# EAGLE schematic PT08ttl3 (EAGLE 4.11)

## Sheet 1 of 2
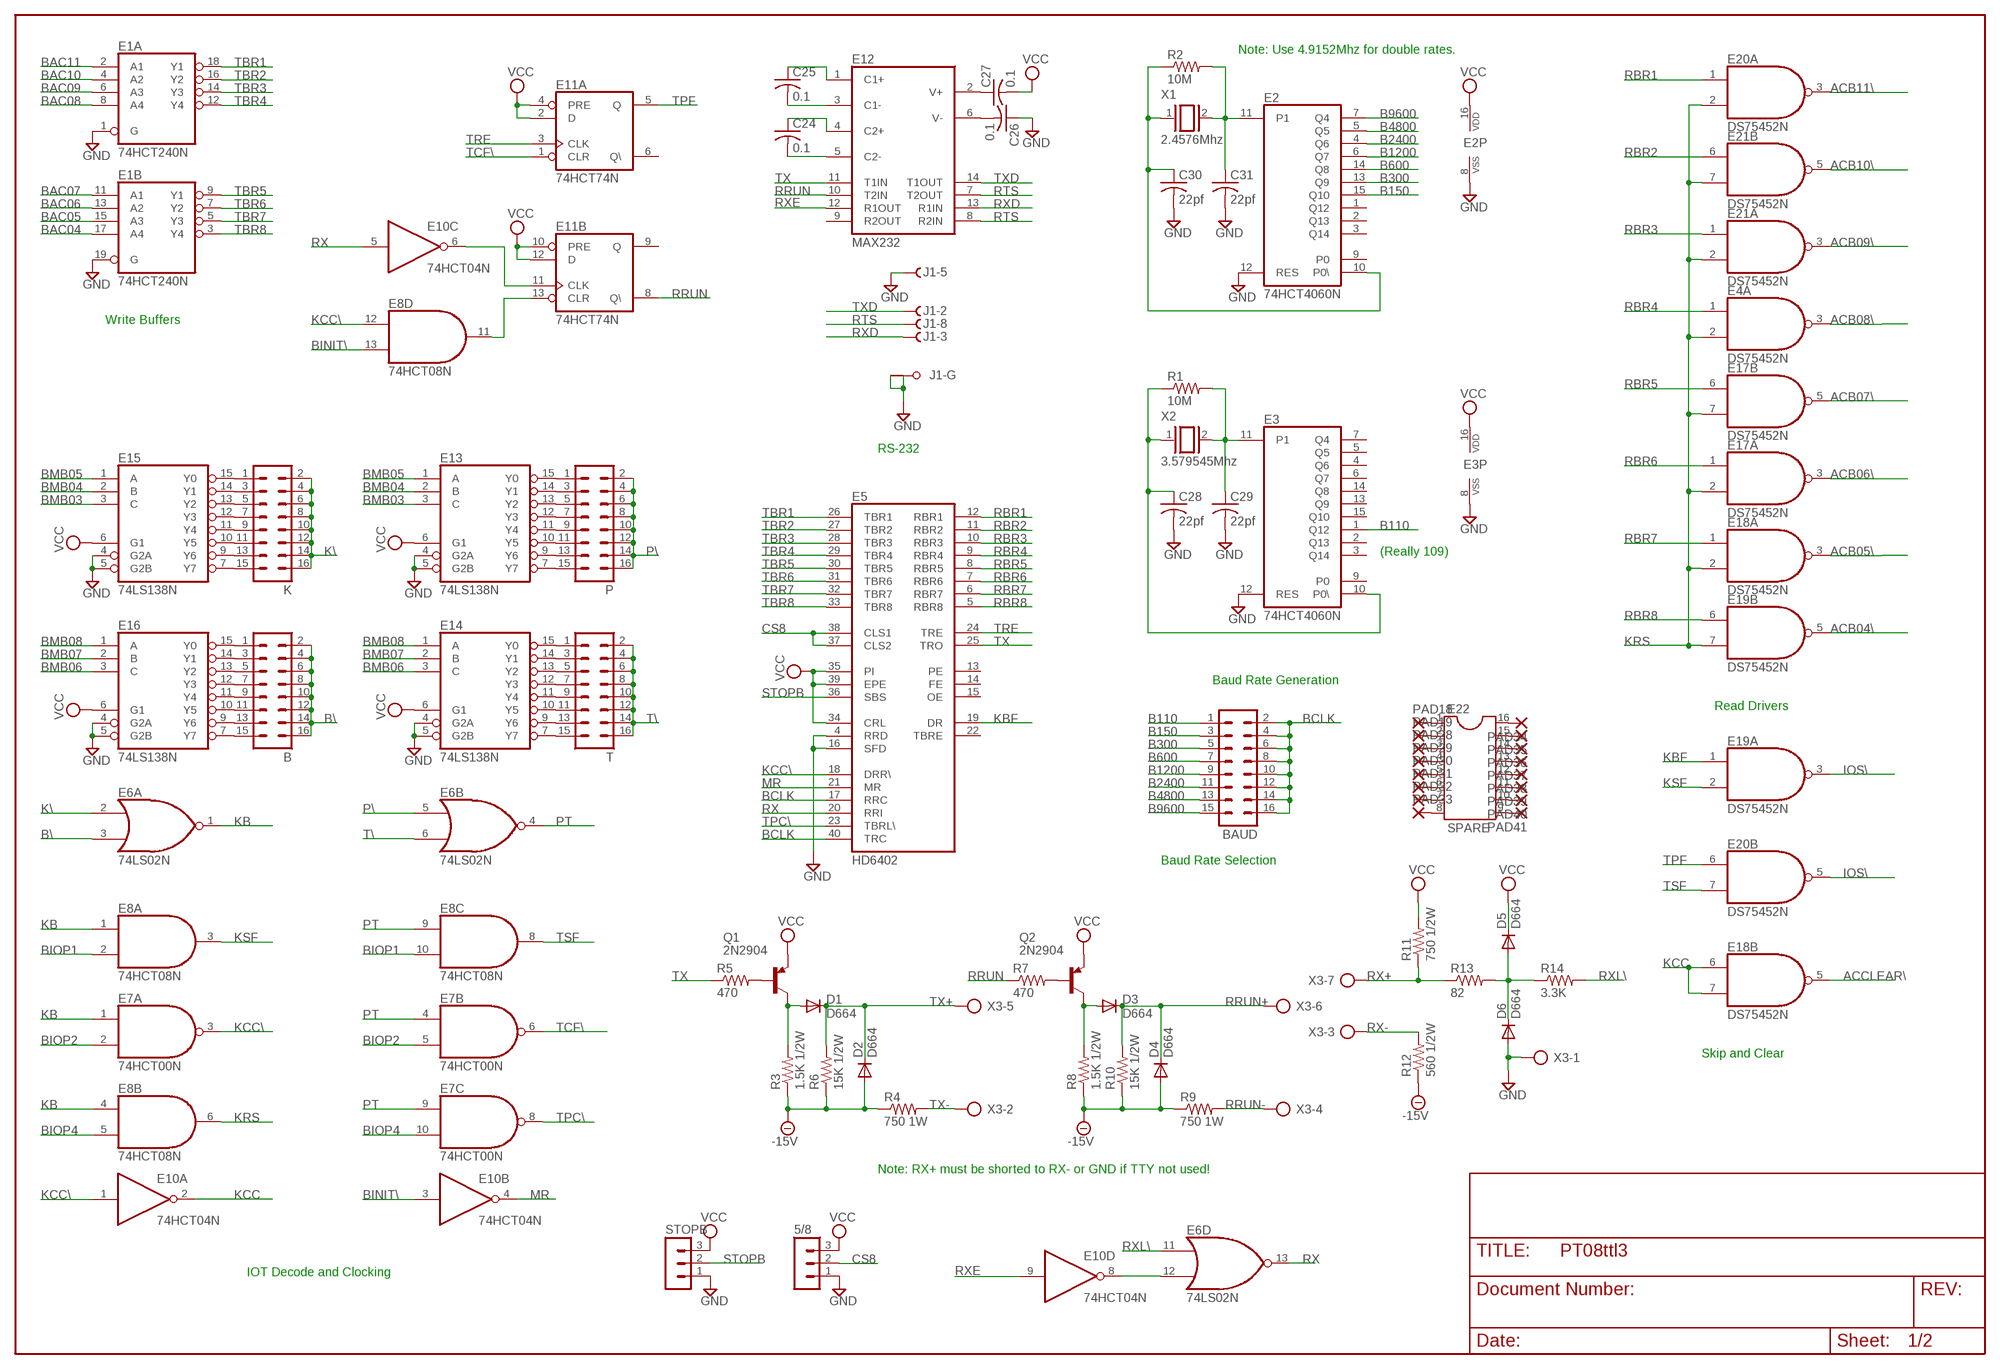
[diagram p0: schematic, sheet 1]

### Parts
5/8  MA03-1  [MA03-1]
B  MA08-2  [MA08-2]
BAUD  MA08-2  [MA08-2]
C24  0.1  C-US050-025X075  [C050-025X075]
C25  0.1  C-US050-025X075  [C050-025X075]
C26  0.1  C-US050-025X075  [C050-025X075]
C27  0.1  C-US050-025X075  [C050-025X075]
C28  22pf  C-US050-025X075  [C050-025X075]
C29  22pf  C-US050-025X075  [C050-025X075]
C30  22pf  C-US050-025X075  [C050-025X075]
C31  22pf  C-US050-025X075  [C050-025X075]
D1  D664  1N4148  [DO35-10]
D2  D664  1N4148  [DO35-10]
D3  D664  1N4148  [DO35-10]
D4  D664  1N4148  [DO35-10]
D5  D664  1N4148  [DO35-10]
D6  D664  1N4148  [DO35-10]
E1  74HCT240N  [DIL20]
E2  74HCT4060N  4060N  [DIL16]
E3  74HCT4060N  4060N  [DIL16]
E4  DS75452N  [DIL08]
E5  HD6402  [DIL40]
E6  74LS02N  [DIL14]
E7  74HCT00N  [DIL14]
E8  74HCT08N  [DIL14]
E10  74HCT04N  [DIL14]
E11  74HCT74N  [DIL14]
E12  MAX232  [DIL16]
E13  74LS138N  [DIL16]
E14  74LS138N  [DIL16]
E15  74LS138N  [DIL16]
E16  74LS138N  [DIL16]
E17  DS75452N  [DIL08]
E18  DS75452N  [DIL08]
E19  DS75452N  [DIL08]
E20  DS75452N  [DIL08]
E21  DS75452N  [DIL08]
E22  SPARE  DIL16  [DIL16]
J1  F09HPS  [F09HP]
K  MA08-2  [MA08-2]
P  MA08-2  [MA08-2]
PAD18  1,6/0,8  [1,6/0,8]
PAD19  1,6/0,8  [1,6/0,8]
PAD28  1,6/0,8  [1,6/0,8]
PAD29  1,6/0,8  [1,6/0,8]
PAD30  1,6/0,8  [1,6/0,8]
PAD31  1,6/0,8  [1,6/0,8]
PAD32  1,6/0,8  [1,6/0,8]
PAD33  1,6/0,8  [1,6/0,8]
PAD34  1,6/0,8  [1,6/0,8]
PAD35  1,6/0,8  [1,6/0,8]
PAD36  1,6/0,8  [1,6/0,8]
PAD37  1,6/0,8  [1,6/0,8]
PAD38  1,6/0,8  [1,6/0,8]
PAD39  1,6/0,8  [1,6/0,8]
PAD40  1,6/0,8  [1,6/0,8]
PAD41  1,6/0,8  [1,6/0,8]
Q1  2N2904  [TO39]
Q2  2N2904  [TO39]
R1  10M  R-US_0207/10  [0207/10]
R2  10M  R-US_0207/10  [0207/10]
R3  1.5K 1/2W  R-US_0207/10  [0207/10]
R4  750 1W  R-US_0207/10  [0207/10]
R5  470  R-US_0207/10  [0207/10]
R6  15K 1/2W  R-US_0207/10  [0207/10]
R7  470  R-US_0207/10  [0207/10]
R8  1.5K 1/2W  R-US_0207/10  [0207/10]
R9  750 1W  R-US_0207/10  [0207/10]
R10  15K 1/2W  R-US_0207/10  [0207/10]
R11  750 1/2W  R-US_0207/10  [0207/10]
R12  560 1/2W  R-US_0207/10  [0207/10]
R13  82  R-US_0207/10  [0207/10]
R14  3.3K  R-US_0207/10  [0207/10]
STOPB  MA03-1  [MA03-1]
T  MA08-2  [MA08-2]
X1  2.4576Mhz  XTAL/S  [QS]
X2  3.579545Mhz  XTAL/S  [QS]
X3  AK300/7  [AK300/7]

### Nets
-15V [supply]: D2.A D4.A R3.1 R4.1 R6.1 R8.1 R9.1 R10.1 R12.1 ; also sheet 2
ACB04\: E19.5(B:O) ; also sheet 2
ACB05\: E18.3(A:O) ; also sheet 2
ACB06\: E17.3(A:O) ; also sheet 2
ACB07\: E17.5(B:O) ; also sheet 2
ACB08\: E4.3(A:O) ; also sheet 2
ACB09\: E21.3(A:O) ; also sheet 2
ACB10\: E21.5(B:O) ; also sheet 2
ACB11\: E20.3(A:O) ; also sheet 2
ACCLEAR\: E18.5(B:O) ; also sheet 2
B110: BAUD.1 E3.1(Q12)
B150: BAUD.3 E2.15(Q10)
B300: BAUD.5 E2.13(Q9)
B600: BAUD.7 E2.14(Q8)
B1200: BAUD.9 E2.6(Q7)
B2400: BAUD.11 E2.4(Q6)
B4800: BAUD.13 E2.5(Q5)
B9600: BAUD.15 E2.7(Q4)
B\: B.2 B.4 B.6 B.8 B.10 B.12 B.14 B.16 E6.3(A:I1)
BAC04: E1.17(B:A4) ; also sheet 2
BAC05: E1.15(B:A3) ; also sheet 2
BAC06: E1.13(B:A2) ; also sheet 2
BAC07: E1.11(B:A1) ; also sheet 2
BAC08: E1.8(A:A4) ; also sheet 2
BAC09: E1.6(A:A3) ; also sheet 2
BAC10: E1.4(A:A2) ; also sheet 2
BAC11: E1.2(A:A1) ; also sheet 2
BCLK: BAUD.2 BAUD.4 BAUD.6 BAUD.8 BAUD.10 BAUD.12 BAUD.14 BAUD.16 E5.17(RRC) E5.40(TRC)
BINIT\: E8.13(D:I1) E10.3(B:I) ; also sheet 2
BIOP1: E8.2(A:I1) E8.10(C:I1) ; also sheet 2
BIOP2: E7.2(A:I1) E7.5(B:I1) ; also sheet 2
BIOP4: E7.10(C:I1) E8.5(B:I1) ; also sheet 2
BMB03: E13.3(C) E15.3(C) ; also sheet 2
BMB04: E13.2(B) E15.2(B) ; also sheet 2
BMB05: E13.1(A) E15.1(A) ; also sheet 2
BMB06: E14.3(C) E16.3(C) ; also sheet 2
BMB07: E14.2(B) E16.2(B) ; also sheet 2
BMB08: E14.1(A) E16.1(A) ; also sheet 2
CS8: 5/8.2 E5.37(CLS2) E5.38(CLS1)
GND [supply]: 5/8.1 C26.1 C28.2 C29.2 C30.2 C31.2 D6.A E1.1(A:G) E1.19(B:G) E2.8(VSS) E2.12(RES) E3.8(VSS) E3.12(RES) E5.4(RRD) E5.16(SFD) E13.4(G2A) E13.5(G2B) E14.4(G2A) E14.5(G2B) E15.4(G2A) E15.5(G2B) E16.4(G2A) E16.5(G2B) J1.5(-5:F) J1.G1(-G:G1) J1.G2(-G:G2) STOPB.1 X3.1 ; also sheet 2
IOS\: E19.3(A:O) E20.5(B:O) ; also sheet 2
K\: E6.2(A:I0) K.2 K.4 K.6 K.8 K.10 K.12 K.14 K.16
KB: E6.1(A:O) E7.1(A:I0) E8.1(A:I0) E8.4(B:I0)
KBF: E5.19(DR) E19.1(A:I0) ; also sheet 2
KCC: E10.2(A:O) E18.6(B:I0) E18.7(B:I1)
KCC\: E5.18(DRR\) E7.3(A:O) E8.12(D:I0) E10.1(A:I)
KRS: E4.2(A:I1) E8.6(B:O) E17.2(A:I1) E17.7(B:I1) E18.2(A:I1) E19.7(B:I1) E20.2(A:I1) E21.2(A:I1) E21.7(B:I1)
KSF: E8.3(A:O) E19.2(A:I1)
MR: E5.21(MR) E10.4(B:O)
N$1: B.13 E16.9(Y6)
N$5: B.1 E16.15(Y0)
N$6: B.3 E16.14(Y1)
N$7: B.5 E16.13(Y2)
N$8: B.7 E16.12(Y3)
N$9: B.9 E16.11(Y4)
N$10: B.11 E16.10(Y5)
N$11: B.15 E16.7(Y7)
N$13: C29.1 E3.11(P1) R1.2 X2.2
N$14: C28.1 E3.10(P0\) R1.1 X2.1
N$15 [supply]: C26.2 E12.6(V-)
N$16 [supply]: C27.1 E12.2(V+)
N$17: Q1.2(B) R5.2
N$18: D1.A Q1.3(C) R3.2
N$19: Q2.2(B) R7.2
N$20: D3.A Q2.3(C) R8.2
N$22: C24.2 E12.5(C2-)
N$23: C30.1 E2.10(P0\) R2.1 X1.1
N$24: D5.A D6.C R13.2 R14.1
N$25: C31.1 E2.11(P1) R2.2 X1.2
N$26: E8.11(D:O) E11.13(B:CLR)
N$27: E6.12(D:I1) E10.8(D:O)
N$29: E10.6(C:O) E11.11(B:CLK)
N$32: C25.2 E12.3(C1-)
N$34: E22.1 PAD18.1(P)
N$41: E22.2 PAD19.1(P)
N$43: E22.3 PAD28.1(P)
N$44: C24.1 E12.4(C2+)
N$45: C25.1 E12.1(C1+)
N$49: E14.15(Y0) T.1
N$50: E22.4 PAD29.1(P)
N$51: E22.5 PAD30.1(P)
N$52: E22.6 PAD31.1(P)
N$53: E22.7 PAD32.1(P)
N$54: E22.8 PAD33.1(P)
N$55: E22.16 PAD34.1(P)
N$56: E22.15 PAD35.1(P)
N$57: E22.14 PAD36.1(P)
N$58: E22.13 PAD37.1(P)
N$59: E22.12 PAD38.1(P)
N$61: E22.11 PAD39.1(P)
N$68: E22.10 PAD40.1(P)
N$69: E22.9 PAD41.1(P)
N$90: E15.15(Y0) K.1
N$91: E15.14(Y1) K.3
N$97: E15.13(Y2) K.5
N$109: E15.12(Y3) K.7
N$112: E15.11(Y4) K.9
N$113: E15.10(Y5) K.11
N$114: E15.7(Y7) K.15
N$115: E15.9(Y6) K.13
N$116: E14.14(Y1) T.3
N$117: E14.13(Y2) T.5
N$118: E14.12(Y3) T.7
N$119: E14.11(Y4) T.9
N$120: E14.10(Y5) T.11
N$121: E14.7(Y7) T.15
N$122: E14.9(Y6) T.13
N$123: E13.15(Y0) P.1
N$124: E13.14(Y1) P.3
N$125: E13.13(Y2) P.5
N$126: E13.12(Y3) P.7
N$127: E13.11(Y4) P.9
N$128: E13.10(Y5) P.11
N$129: E13.7(Y7) P.15
N$130: E13.9(Y6) P.13
P\: E6.5(B:I0) P.2 P.4 P.6 P.8 P.10 P.12 P.14 P.16
PT: E6.4(B:O) E7.4(B:I0) E7.9(C:I0) E8.9(C:I0)
RBR1: E5.12(RBR1) E20.1(A:I0)
RBR2: E5.11(RBR2) E21.6(B:I0)
RBR3: E5.10(RBR3) E21.1(A:I0)
RBR4: E4.1(A:I0) E5.9(RBR4)
RBR5: E5.8(RBR5) E17.6(B:I0)
RBR6: E5.7(RBR6) E17.1(A:I0)
RBR7: E5.6(RBR7) E18.1(A:I0)
RBR8: E5.5(RBR8) E19.6(B:I0)
RRUN: E11.8(B:Q\) E12.10(T2IN) R7.1
RRUN+: D3.C D4.C R10.2 X3.6
RRUN-: R9.2 X3.4
RTS: E12.7(T2OUT) E12.8(R2IN) J1.8(-8:F)
RX: E5.20(RRI) E6.13(D:O) E10.5(C:I)
RX+: R11.1 R13.1 X3.7
RX-: R12.2 X3.3
RXD: E12.13(R1IN) J1.3(-3:F)
RXE: E10.9(D:I) E12.12(R1OUT)
RXL\: E6.11(D:I0) R14.2
STOPB: E5.36(SBS) STOPB.2
T\: E6.6(B:I1) T.2 T.4 T.6 T.8 T.10 T.12 T.14 T.16
TBR1: E1.18(A:Y1) E5.26(TBR1)
TBR2: E1.16(A:Y2) E5.27(TBR2)
TBR3: E1.14(A:Y3) E5.28(TBR3)
TBR4: E1.12(A:Y4) E5.29(TBR4)
TBR5: E1.9(B:Y1) E5.30(TBR5)
TBR6: E1.7(B:Y2) E5.31(TBR6)
TBR7: E1.5(B:Y3) E5.32(TBR7)
TBR8: E1.3(B:Y4) E5.33(TBR8)
TCF\: E7.6(B:O) E11.1(A:CLR)
TPC\: E5.23(TBRL\) E7.8(C:O)
TPF: E11.5(A:Q) E20.6(B:I0) ; also sheet 2
TRE: E5.24(TRE) E11.3(A:CLK)
TSF: E8.8(C:O) E20.7(B:I1)
TX: E5.25(TRO) E12.11(T1IN) R5.1
TX+: D1.C D2.C R6.2 X3.5
TX-: R4.2 X3.2
TXD: E12.14(T1OUT) J1.2(-2:F)
VCC [supply]: 5/8.3 C27.2 D5.C E2.16(VDD) E3.16(VDD) E5.34(CRL) E5.35(PI) E5.39(EPE) E11.2(A:D) E11.4(A:PRE) E11.10(B:PRE) E11.12(B:D) E13.6(G1) E14.6(G1) E15.6(G1) E16.6(G1) Q1.1(E) Q2.1(E) R11.2 STOPB.3 ; also sheet 2
Unconnected: E2.1(Q12) E2.2(Q13) E2.3(Q14) E2.9(P0) E3.2(Q13) E3.3(Q14) E3.4(Q6) E3.5(Q5) E3.6(Q7) E3.7(Q4) E3.9(P0) E3.13(Q9) E3.14(Q8) E3.15(Q10) E5.13(PE) E5.14(FE) E5.15(OE) E5.22(TBRE) E11.6(A:Q\) E11.9(B:Q) E12.9(R2OUT) J1.1(-1:F) J1.4(-4:F) J1.6(-6:F) J1.7(-7:F) J1.9(-9:F)

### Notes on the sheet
- Note: Use 4.9152Mhz for double rates.
- Write Buffers
- RS-232
- (Really 109)
- Baud Rate Generation
- Read Drivers
- Baud Rate Selection
- Skip and Clear
- Note: RX+ must be shorted to RX- or GND if TTY not used!
- IOT Decode and Clocking

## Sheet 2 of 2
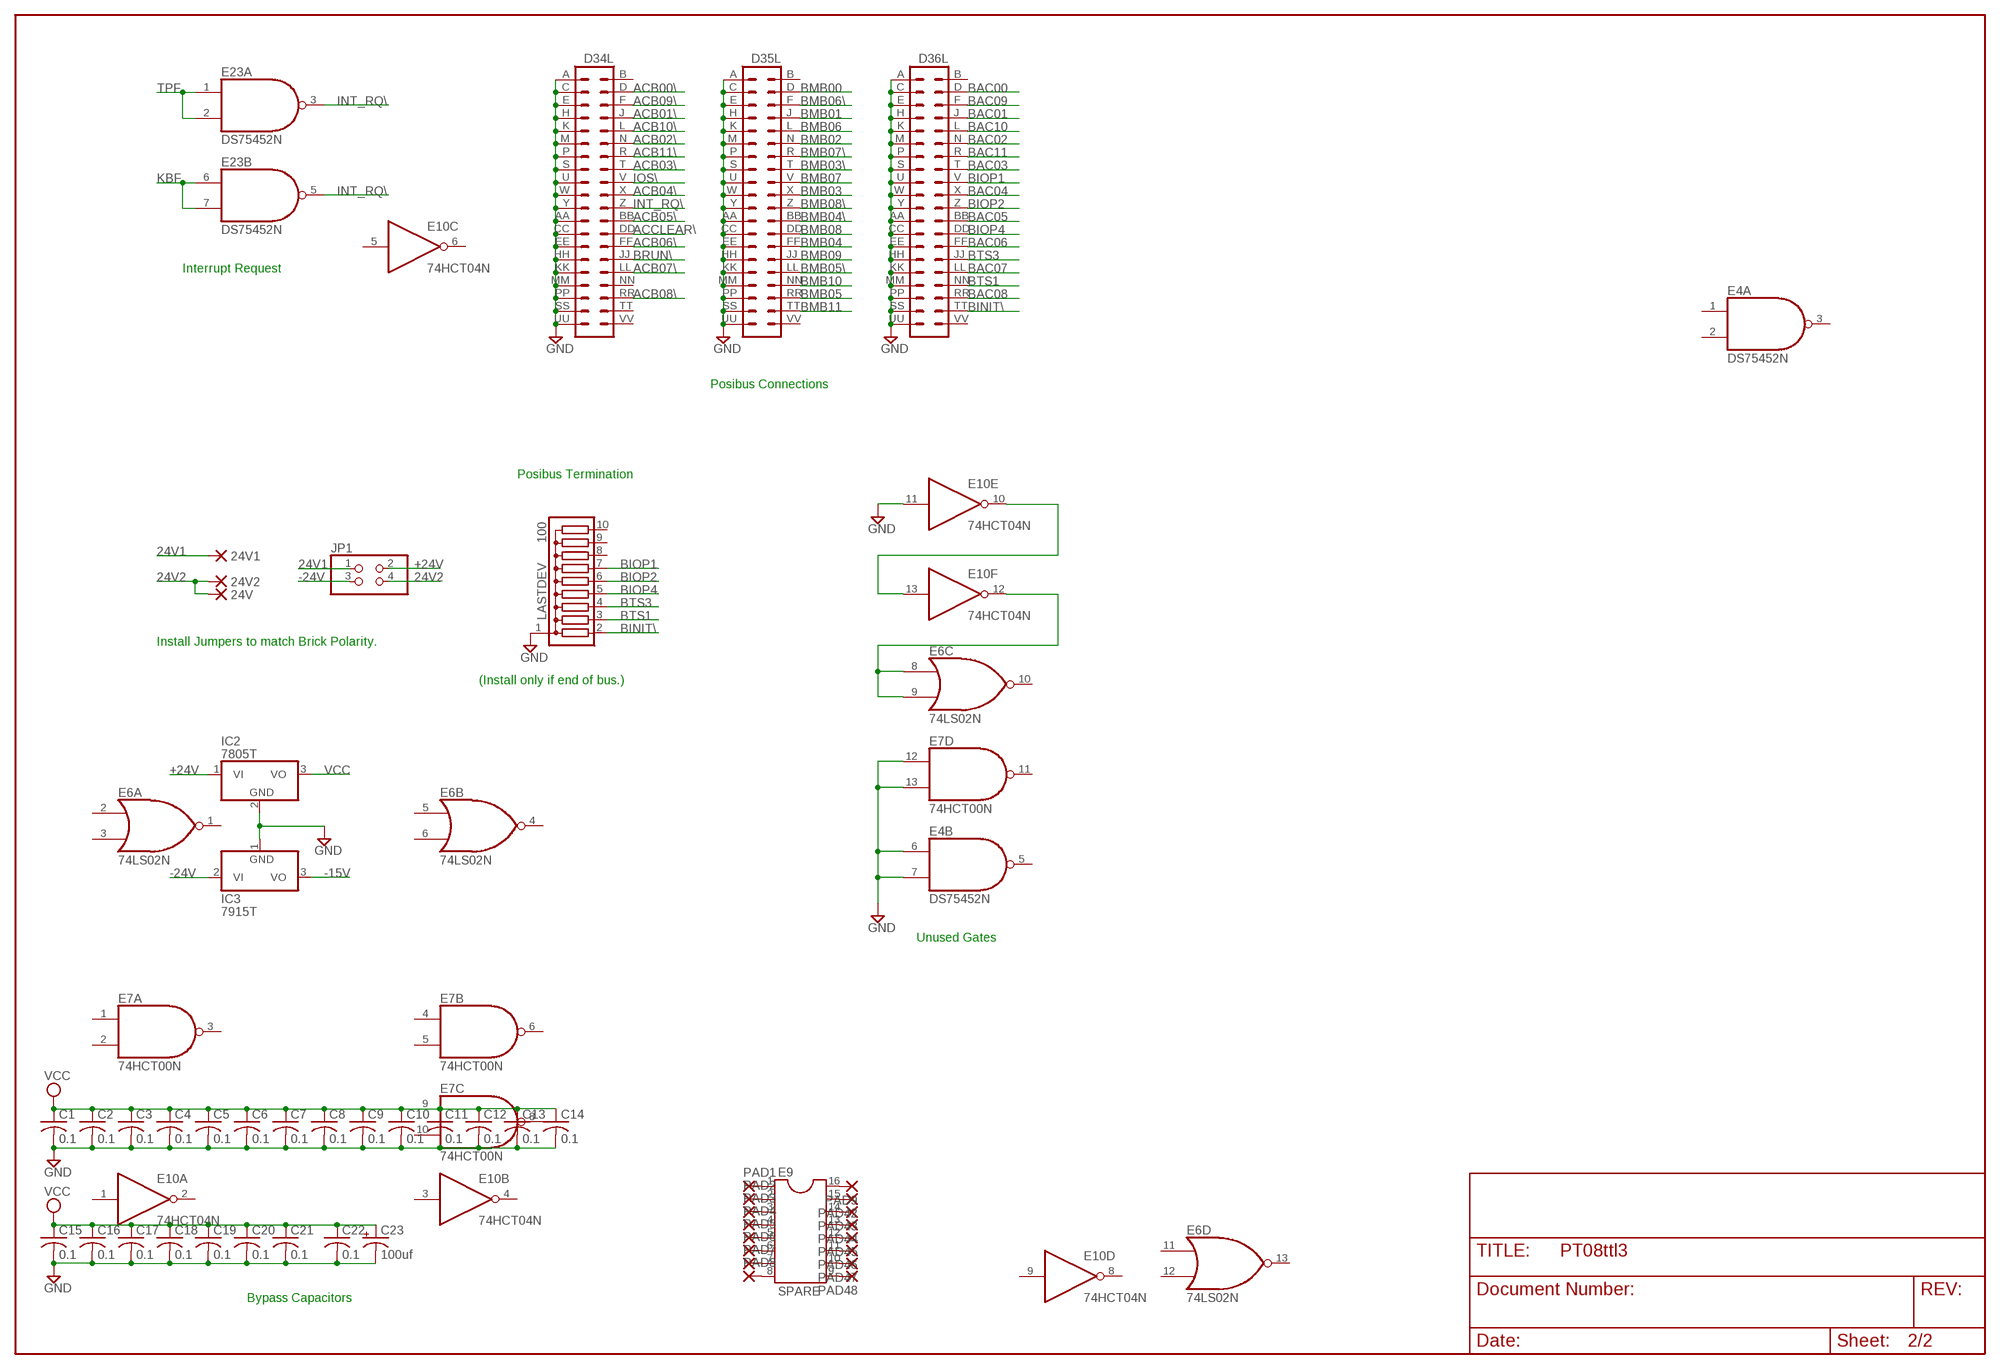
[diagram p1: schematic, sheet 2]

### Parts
24V  PAD-0820  [0820]
24V1  PAD-0820  [0820]
24V2  PAD-0820  [0820]
C1  0.1  C-US050-025X075  [C050-025X075]
C2  0.1  C-US050-025X075  [C050-025X075]
C3  0.1  C-US050-025X075  [C050-025X075]
C4  0.1  C-US050-025X075  [C050-025X075]
C5  0.1  C-US050-025X075  [C050-025X075]
C6  0.1  C-US050-025X075  [C050-025X075]
C7  0.1  C-US050-025X075  [C050-025X075]
C8  0.1  C-US050-025X075  [C050-025X075]
C9  0.1  C-US050-025X075  [C050-025X075]
C10  0.1  C-US050-025X075  [C050-025X075]
C11  0.1  C-US050-025X075  [C050-025X075]
C12  0.1  C-US050-025X075  [C050-025X075]
C13  0.1  C-US050-025X075  [C050-025X075]
C14  0.1  C-US050-025X075  [C050-025X075]
C15  0.1  C-US050-025X075  [C050-025X075]
C16  0.1  C-US050-025X075  [C050-025X075]
C17  0.1  C-US050-025X075  [C050-025X075]
C18  0.1  C-US050-025X075  [C050-025X075]
C19  0.1  C-US050-025X075  [C050-025X075]
C20  0.1  C-US050-025X075  [C050-025X075]
C21  0.1  C-US050-025X075  [C050-025X075]
C22  0.1  C-US050-025X075  [C050-025X075]
C23  100uf  CPOL-USE22-9AXIAL  [E22-9]
D34L  DEC40PINH  [DEC40PINH]
D35L  DEC40PINH  [DEC40PINH]
D36L  DEC40PINH  [DEC40PINH]
E9  SPARE  DIL16  [DIL16]
E23  DS75452N  [DIL08]
IC2  7805T  [TO220H]
IC3  7915T  [TO220H]
JP1  PINHD-2X2  [2X02]
LASTDEV  100  G09R  [SIL10]
PAD1  1,6/0,8  [1,6/0,8]
PAD2  1,6/0,8  [1,6/0,8]
PAD3  1,6/0,8  [1,6/0,8]
PAD4  1,6/0,8  [1,6/0,8]
PAD5  1,6/0,8  [1,6/0,8]
PAD6  1,6/0,8  [1,6/0,8]
PAD7  1,6/0,8  [1,6/0,8]
PAD8  1,6/0,8  [1,6/0,8]
PAD9  1,6/0,8  [1,6/0,8]
PAD42  1,6/0,8  [1,6/0,8]
PAD43  1,6/0,8  [1,6/0,8]
PAD44  1,6/0,8  [1,6/0,8]
PAD45  1,6/0,8  [1,6/0,8]
PAD46  1,6/0,8  [1,6/0,8]
PAD47  1,6/0,8  [1,6/0,8]
PAD48  1,6/0,8  [1,6/0,8]

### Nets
24V1 [supply]: 24V1.P$1(P) JP1.1
24V2 [supply]: 24V2.P$1(P) 24V.P$1(P) JP1.4
+24V [supply]: IC2.1(VI) JP1.2
-15V [supply]: IC3.3(VO) ; also sheet 1
-24V [supply]: IC3.2(VI) JP1.3
ACB00\: D34L.D
ACB01\: D34L.J
ACB02\: D34L.N
ACB03\: D34L.T
ACB04\: D34L.X ; also sheet 1
ACB05\: D34L.BB ; also sheet 1
ACB06\: D34L.FF ; also sheet 1
ACB07\: D34L.LL ; also sheet 1
ACB08\: D34L.RR ; also sheet 1
ACB09\: D34L.F ; also sheet 1
ACB10\: D34L.L ; also sheet 1
ACB11\: D34L.R ; also sheet 1
ACCLEAR\: D34L.DD ; also sheet 1
BAC00: D36L.D
BAC01: D36L.J
BAC02: D36L.N
BAC03: D36L.T
BAC04: D36L.X ; also sheet 1
BAC05: D36L.BB ; also sheet 1
BAC06: D36L.FF ; also sheet 1
BAC07: D36L.LL ; also sheet 1
BAC08: D36L.RR ; also sheet 1
BAC09: D36L.F ; also sheet 1
BAC10: D36L.L ; also sheet 1
BAC11: D36L.R ; also sheet 1
BINIT\: D36L.TT LASTDEV.2 ; also sheet 1
BIOP1: D36L.V LASTDEV.7 ; also sheet 1
BIOP2: D36L.Z LASTDEV.6 ; also sheet 1
BIOP4: D36L.DD LASTDEV.5 ; also sheet 1
BMB00: D35L.D
BMB01: D35L.J
BMB02: D35L.N
BMB03: D35L.X ; also sheet 1
BMB03\: D35L.T
BMB04: D35L.FF ; also sheet 1
BMB04\: D35L.BB
BMB05: D35L.RR ; also sheet 1
BMB05\: D35L.LL
BMB06: D35L.L ; also sheet 1
BMB06\: D35L.F
BMB07: D35L.V ; also sheet 1
BMB07\: D35L.R
BMB08: D35L.DD ; also sheet 1
BMB08\: D35L.Z
BMB09: D35L.JJ
BMB10: D35L.NN
BMB11: D35L.TT
BRUN\: D34L.JJ
BTS1: D36L.NN LASTDEV.3
BTS3: D36L.JJ LASTDEV.4
GND [supply]: C1.2 C2.2 C3.2 C4.2 C5.2 C6.2 C7.2 C8.2 C9.2 C10.2 C11.2 C12.2 C13.2 C14.2 C15.2 C16.2 C17.2 C18.2 C19.2 C20.2 C21.2 C22.2 C23.- D34L.A D34L.AA D34L.C D34L.CC D34L.E D34L.EE D34L.H D34L.HH D34L.K D34L.KK D34L.M D34L.MM D34L.P D34L.PP D34L.S D34L.SS D34L.U D34L.UU D34L.W D34L.Y D35L.A D35L.AA D35L.C D35L.CC D35L.E D35L.EE D35L.H D35L.HH D35L.K D35L.KK D35L.M D35L.MM D35L.P D35L.PP D35L.S D35L.SS D35L.U D35L.UU D35L.W D35L.Y D36L.A D36L.AA D36L.C D36L.CC D36L.E D36L.EE D36L.H D36L.HH D36L.K D36L.KK D36L.M D36L.MM D36L.P D36L.PP D36L.S D36L.SS D36L.U D36L.UU D36L.W D36L.Y E4.6(B:I0) E4.7(B:I1) E7.12(D:I0) E7.13(D:I1) E10.11(E:I) IC2.2(GND) IC3.1(GND) LASTDEV.1 ; also sheet 1
INT_RQ\: D34L.Z E23.3(A:O) E23.5(B:O)
IOS\: D34L.V ; also sheet 1
KBF: E23.6(B:I0) E23.7(B:I1) ; also sheet 1
N$2: E9.1 PAD1.1(P)
N$3: E9.2 PAD2.1(P)
N$4: E9.3 PAD3.1(P)
N$12: E9.4 PAD4.1(P)
N$21: E9.5 PAD5.1(P)
N$30 [supply]: E10.10(E:O) E10.13(F:I)
N$31: E9.6 PAD6.1(P)
N$33: E9.7 PAD7.1(P)
N$35: E9.8 PAD8.1(P)
N$37: E9.16 PAD9.1(P)
N$38: E9.15 PAD42.1(P)
N$39: E9.14 PAD43.1(P)
N$40: E9.13 PAD44.1(P)
N$42: E9.12 PAD45.1(P)
N$46: E9.11 PAD46.1(P)
N$47: E9.10 PAD47.1(P)
N$48: E9.9 PAD48.1(P)
N$60 [supply]: E6.8(C:I0) E6.9(C:I1) E10.12(F:O)
TPF: E23.1(A:I0) E23.2(A:I1) ; also sheet 1
VCC [supply]: C1.1 C2.1 C3.1 C4.1 C5.1 C6.1 C7.1 C8.1 C9.1 C10.1 C11.1 C12.1 C13.1 C14.1 C15.1 C16.1 C17.1 C18.1 C19.1 C20.1 C21.1 C22.1 C23.+ IC2.3(VO) ; also sheet 1
Unconnected: D34L.B D34L.NN D34L.TT D34L.VV D35L.B D35L.VV D36L.B D36L.VV E4.5(B:O) E6.10(C:O) E7.11(D:O) LASTDEV.8 LASTDEV.9 LASTDEV.10

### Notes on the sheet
- Interrupt Request
- Posibus Connections
- Posibus Termination
- Install Jumpers to match Brick Polarity.
- (Install only if end of bus.)
- Unused Gates
- Bypass Capacitors

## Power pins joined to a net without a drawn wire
GND: E1.10(P:GND) E4.4(P:GND) E5.3(GND) E6.7(P:GND) E7.7(P:GND) E8.7(P:GND) E10.7(P:GND) E11.7(P:GND) E12.15(GND) E13.8(GND) E14.8(GND) E15.8(GND) E16.8(GND) E17.4(P:GND) E18.4(P:GND) E19.4(P:GND) E20.4(P:GND) E21.4(P:GND) E23.4(P:GND)
VCC: E1.20(P:VCC) E4.8(P:VCC) E5.1(VCC) E6.14(P:VCC) E7.14(P:VCC) E8.14(P:VCC) E10.14(P:VCC) E11.14(P:VCC) E12.16(VCC) E13.16(VCC) E14.16(VCC) E15.16(VCC) E16.16(VCC) E17.8(P:VCC) E18.8(P:VCC) E19.8(P:VCC) E20.8(P:VCC) E21.8(P:VCC) E23.8(P:VCC)

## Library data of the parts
5/8 STOPB = con-lstb:MA03-1: PIN HEADER
24V 24V1 24V2 = dpads:PAD: WIRE PAD
B BAUD K P T = con-lstb:MA08-2: PIN HEADER
C1-C22 C24-C31 = rcl:C-US: CAPACITOR, American symbol
C23 = rcl:CPOL-US: POLARIZED CAPACITOR, American symbol
D1-D6 = diode:1N4148: DIODE
D34L D35L D36L = dec-con:DEC40PIN: PIN HEADER
E1 = 74xx-jameco:74*240: Octal BUFFER and LINE DRIVER, 3-state
E2 E3 = 40xx:4060: 14-stage binary/ripple COUNTER
E4 E17-E21 E23 = 74xx-jameco:DS75452: Quad 2-input NAND gate, open collector output
E5 = micro-harris:HD6402: MICROCONTROLLER/MEMORY DEVICE
E6 = 74xx-us:74*02: Quad 2-input NOR gate
E7 = 74xx-jameco:74*00: Quad 2-input NAND gate
E8 = 74xx-jameco:74*08: Quad 2-input AND gate
E9 E22 = ic-package:DIL16: Dual In Line
E10 = 74xx-jameco:74*04: Hex INVERTER
E11 = 74xx-jameco:74*74: Dual D type positive edge triggered FLIP FLOP, preset and clear
E12 = maxim:MAX232: RS232 TRANSEIVER
E13-E16 = 74xx-jameco:74*138: 3-line to 8-line DECODER/DEMULTIPLEXER
IC2 = linear:78*: Positive VOLTAGE REGULATOR
IC3 = linear:79*: Negative VOLTAGE REGULATOR
J1 = con-subd:F09HPS: SUB-D
JP1 = pinhead:PINHD-2X2: PIN HEADER
LASTDEV = resistor-sil:G09R: SIL RESISTOR
PAD1-PAD9 PAD18 PAD19 PAD28-PAD48 = wirepad:1,6/0,8: THROUGH-HOLE PAD
Q1 Q2 = transistor-pnp:2N2904*: PNP Transistror
R1-R14 = rcl:R-US_: RESISTOR, American symbol
X1 X2 = special:XTAL/S: CRYSTAL
X3 = con-ptr500:AK300/7: CONNECTOR

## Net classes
1 supply: width 0.508 mm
